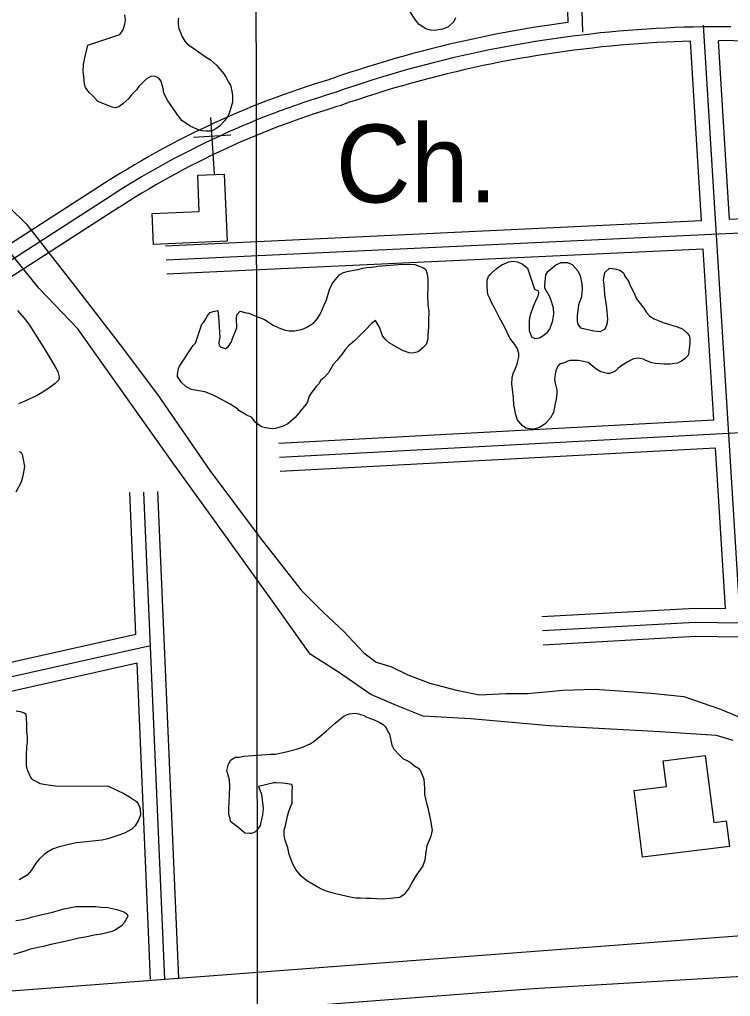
# Model space of a CAD drawing. Extents: x 3313442 to 3351311, y 721974 to 747360.
# Drawn here: x 3333060 to 3333817, y 734997 to 736038 of the extents above; entities that cross this region are included whole.
import ezdxf

# ---------------------------------------------------------------- set-up
doc = ezdxf.new("R2010")
doc.units = 0
for name, color, linetype in [('V-BLDG-OTLN', 7, 'Continuous'), ('V-GRID-MAJR', 7, 'Continuous'), ('V-ROAD-CNTR', 7, 'Continuous'), ('V-SITE-OTLN', 7, 'Continuous'), ('V-SITE-OTLN-IDEN', 7, 'Continuous'), ('V-SITE-VEGE', 7, 'Continuous'), ('V-TOPO-SHOR', 7, 'Continuous')]:
    doc.layers.add(name, color=color, linetype=linetype)

msp = doc.modelspace()

# ---------------------------------------------------------------- linework, layer by layer
at = {"layer": 'V-BLDG-OTLN'}
for points in [[(3333277.6, 735873.2), (3333280.7, 735801.7), (3333202.4, 735798.3), (3333201, 735831.3), (3333251.1, 735833.4), (3333249.4, 735872)], [(3333723.4, 735145.6), (3333714.4, 735216.9), (3333749, 735221.2), (3333745.6, 735248.3), (3333790.3, 735253.9), (3333799.3, 735182.6), (3333812.6, 735184.3), (3333816, 735157.3)]]:
    msp.add_lwpolyline(points, close=True, dxfattribs=at)
at = {"layer": 'V-GRID-MAJR'}
msp.add_spline([(3333324.1, 727373.9), (3333315.3, 733432.2), (3333306.5, 739494), (3333297.7, 745555.7), (3333297.7, 745559.2)], degree=3, dxfattribs=at)
at = {"layer": 'V-ROAD-CNTR'}
for points in [[(3333636.2, 737279.2), (3333654.9, 736173.7), (3333659.3, 736024.5)], [(3333638.9, 736236.6), (3333639.9, 736173.3), (3333644, 736034.9)], [(3333644, 736034.9), (3333616.8, 736030.8), (3333606.8, 736029.3), (3333596.9, 736027.6), (3333587, 736025.9), (3333577, 736024.1), (3333567.1, 736022.2), (3333557.2, 736020.2), (3333547.4, 736018.2), (3333537.5, 736016.1), (3333527.7, 736013.9), (3333517.8, 736011.6), (3333508, 736009.2), (3333498.2, 736006.8), (3333488.5, 736004.3), (3333478.7, 736001.7), (3333469, 735999), (3333459.3, 735996.3), (3333449.6, 735993.4), (3333440, 735990.5), (3333430.3, 735987.6), (3333420.7, 735984.5), (3333411.1, 735981.4), (3333401.6, 735978.2), (3333392.1, 735974.9), (3333389.5, 735974)], [(3333817.6, 736030.2), (3333807.7, 736030.3), (3333797.7, 736030.2), (3333787.7, 736030.1), (3333777.8, 736029.9), (3333767.8, 736029.7), (3333757.9, 736029.3), (3333747.9, 736028.9), (3333738, 736028.4), (3333728, 736027.8), (3333718.1, 736027.1), (3333708.1, 736026.4), (3333698.2, 736025.5), (3333688.3, 736024.6), (3333678.4, 736023.6), (3333668.5, 736022.5), (3333658.6, 736021.4), (3333648.7, 736020.2), (3333638.8, 736018.9), (3333628.9, 736017.5), (3333619.1, 736016), (3333609.2, 736014.5), (3333599.4, 736012.8), (3333589.6, 736011.1), (3333579.8, 736009.3), (3333570, 736007.5), (3333560.2, 736005.5), (3333550.5, 736003.5), (3333540.7, 736001.4), (3333531, 735999.3), (3333521.3, 735997), (3333511.6, 735994.7), (3333501.9, 735992.3), (3333492.3, 735989.8), (3333482.6, 735987.2), (3333473, 735984.6), (3333463.5, 735981.9), (3333453.9, 735979.1), (3333444.3, 735976.2), (3333434.8, 735973.3), (3333425.3, 735970.2), (3333415.9, 735967.1), (3333406.4, 735964), (3333397, 735960.7), (3333394.4, 735959.8)], [(3333827.7, 735395.4), (3333788.5, 736031.8)], [(3333774.5, 736015), (3333748.6, 736013.9), (3333738.8, 736013.4), (3333729, 736012.8), (3333719.1, 736012.1), (3333709.3, 736011.4), (3333699.5, 736010.6), (3333689.7, 736009.7), (3333679.9, 736008.7), (3333670.1, 736007.6), (3333660.4, 736006.5), (3333650.6, 736005.3), (3333640.8, 736004), (3333631.1, 736002.6), (3333621.3, 736001.2), (3333611.6, 735999.7), (3333601.9, 735998), (3333592.2, 735996.4), (3333582.5, 735994.6), (3333572.8, 735992.8), (3333563.2, 735990.8), (3333553.6, 735988.9), (3333543.9, 735986.8), (3333534.3, 735984.6), (3333524.7, 735982.4), (3333515.2, 735980.1), (3333505.6, 735977.7), (3333496.1, 735975.3), (3333486.6, 735972.7), (3333477.1, 735970.1), (3333467.6, 735967.4), (3333458.2, 735964.7), (3333448.7, 735961.9), (3333439.3, 735958.9), (3333429.9, 735956), (3333420.6, 735952.9), (3333411.3, 735949.8), (3333401.9, 735946.5), (3333399.4, 735945.6)], [(3333786.3, 735823.4), (3333774.5, 736015)], [(3333856.9, 736014.2), (3333847, 736014.6), (3333837.2, 736014.9), (3333804.5, 736015.6)], [(3333816.2, 735824.8), (3333804.5, 736015.4)], [(3333390.1, 735974.1), (3333381.8, 735971.6), (3333373.4, 735969), (3333365.1, 735966.3), (3333356.8, 735963.5), (3333348.5, 735960.6), (3333340.3, 735957.7), (3333332, 735954.7), (3333323.8, 735951.6), (3333315.7, 735948.4), (3333307.5, 735945.2), (3333299.4, 735941.8), (3333291.4, 735938.5), (3333283.3, 735935), (3333275.3, 735931.4), (3333267.3, 735927.8), (3333259.4, 735924.1), (3333251.5, 735920.4), (3333243.6, 735916.5), (3333235.8, 735912.6), (3333228, 735908.6), (3333220.2, 735904.6), (3333212.5, 735900.4), (3333204.8, 735896.2), (3333197.2, 735892), (3333189.6, 735887.6), (3333182, 735883.2), (3333174.5, 735878.7), (3333167, 735874.2), (3333159.6, 735869.6), (3333152.2, 735864.9), (3333149.1, 735862.9)], [(3333394.4, 735959.8), (3333386.2, 735957.3), (3333378, 735954.7), (3333369.8, 735952), (3333361.6, 735949.3), (3333353.5, 735946.5), (3333345.4, 735943.6), (3333337.3, 735940.6), (3333329.2, 735937.6), (3333321.2, 735934.5), (3333313.2, 735931.3), (3333305.2, 735928), (3333297.2, 735924.7), (3333289.3, 735921.2), (3333281.5, 735917.8), (3333273.6, 735914.2), (3333265.8, 735910.6), (3333258, 735906.9), (3333250.3, 735903.1), (3333242.6, 735899.2), (3333234.9, 735895.3), (3333227.2, 735891.3), (3333219.6, 735887.3), (3333212.1, 735883.1), (3333204.6, 735878.9), (3333197.1, 735874.6), (3333189.6, 735870.3), (3333182.2, 735865.9), (3333174.9, 735861.4), (3333167.6, 735856.9), (3333160.3, 735852.2), (3333157.2, 735850.3)], [(3333398.8, 735945.5), (3333390.6, 735943), (3333382.6, 735940.4), (3333374.5, 735937.8), (3333366.4, 735935.1), (3333358.4, 735932.3), (3333350.5, 735929.5), (3333342.5, 735926.6), (3333334.6, 735923.6), (3333326.7, 735920.5), (3333318.8, 735917.4), (3333310.9, 735914.1), (3333303.1, 735910.9), (3333295.3, 735907.5), (3333287.6, 735904.1), (3333279.9, 735900.6), (3333272.2, 735897), (3333264.5, 735893.3), (3333256.9, 735889.6), (3333249.3, 735885.8), (3333241.8, 735882), (3333234.3, 735878.1), (3333226.8, 735874.1), (3333219.3, 735870), (3333211.9, 735865.9), (3333204.6, 735861.7), (3333197.3, 735857.4), (3333190, 735853), (3333182.7, 735848.6), (3333175.5, 735844.2), (3333168.4, 735839.6), (3333165.3, 735837.6)], [(3333149.1, 735862.9), (3332982.5, 735755.7)], [(3333157.2, 735850.3), (3332990.6, 735743)], [(3334322.7, 735848.6), (3333816.2, 735824.8)], [(3333165.3, 735837.6), (3332998.7, 735730.4)], [(3334341.3, 735834.5), (3333215.9, 735781.6)], [(3333786.3, 735823.4), (3333215.1, 735796.5)], [(3333788.1, 735793.5), (3333216.6, 735766.6)], [(3333799.3, 735611.6), (3333788.1, 735793.5)], [(3333336.5, 735571.8), (3334253.7, 735620.9), (3334301.8, 735621.9)], [(3333335.7, 735586.8), (3333799.3, 735611.6)], [(3333337.3, 735556.8), (3333801.2, 735581.7)], [(3333811.7, 735410.7), (3333801.2, 735581.7)], [(3333183.4, 735382.9), (3333176.9, 735534.1)], [(3333214.2, 735015.9), (3333191.9, 735534.7)], [(3333229.2, 735016.5), (3333206.9, 735535.4)], [(3333616, 735402), (3333779.3, 735411.1), (3333811.7, 735410.7)], [(3333616.8, 735387.1), (3333779.7, 735396.1), (3333968.8, 735393.4), (3334181.5, 735402)], [(3333183.4, 735382.9), (3333004.1, 735342.7), (3332892.9, 735305.9)], [(3333617.6, 735372.1), (3333780, 735381.1), (3333969, 735378.4), (3334182.1, 735387)], [(3333199, 735371), (3333008.1, 735328.2), (3332897.6, 735291.7)], [(3333184.7, 735352.4), (3333012.1, 735313.7), (3332902.3, 735277.4)], [(3333199.2, 735015.3), (3333184.7, 735352.4)], [(3329842.9, 734845.2), (3331486.6, 734915.1), (3332609.5, 734970.1), (3334307.5, 735098.7), (3334855.8, 735124.8)], [(3334875.4, 735080.3), (3333607.3, 735005.4), (3332547.3, 734924.9), (3331216.9, 734855.5), (3329722.8, 734799.3)]]:
    msp.add_lwpolyline(points, dxfattribs=at)
at = {"layer": 'V-SITE-OTLN'}
for p, q in [((3333267.2, 735873.6), (3333263.5, 735933.5)), ((3333284.7, 735914.7), (3333244.8, 735912.3))]:
    msp.add_line(p, q, dxfattribs=at)
at = {"layer": 'V-SITE-VEGE'}
for points in [[(3333524, 736039.8), (3333521.9, 736035), (3333515.8, 736029.9), (3333510.4, 736027.8), (3333501.6, 736026.2), (3333497.4, 736026.5), (3333492.4, 736028.2), (3333485.5, 736032.6), (3333481.9, 736036.8), (3333475.9, 736046.2)], [(3333240.8, 736010.2), (3333246.5, 736006.4), (3333250.1, 736003.5), (3333257.2, 735998.5), (3333263.2, 735995), (3333269.5, 735989.4), (3333277.2, 735980), (3333279.6, 735976.1), (3333282.1, 735971.4), (3333284.2, 735967.9), (3333285.7, 735961.7), (3333286.3, 735956.9), (3333286.4, 735949.8), (3333282.9, 735937.9), (3333280.9, 735933.8), (3333277.9, 735929.9), (3333272.7, 735924.5), (3333268.8, 735921.5), (3333263.8, 735919.1), (3333258.5, 735919.1), (3333254.3, 735919.3), (3333248.4, 735921), (3333241.2, 735924.2), (3333232.3, 735930.4), (3333227.8, 735936.3), (3333221.8, 735945.4), (3333217.6, 735951.3), (3333213.4, 735959.6), (3333212.5, 735964.6), (3333210.6, 735972.3), (3333207.6, 735975.9), (3333203.5, 735977.6), (3333199.3, 735977.3), (3333194.3, 735974.3), (3333186.6, 735966.5), (3333184, 735963.2), (3333179, 735957.8), (3333176.1, 735954), (3333169.6, 735948), (3333165.5, 735945), (3333161.9, 735943.8), (3333158.4, 735944.6), (3333142.9, 735950.7), (3333137.5, 735956.6), (3333133.6, 735960.4), (3333129.7, 735965.4), (3333128.8, 735969), (3333127.9, 735977), (3333127.5, 735982.9), (3333127.8, 735990), (3333129.2, 735997.2), (3333132.3, 736010.5), (3333166.3, 736022.1), (3333169.9, 736026.8), (3333171.9, 736033.1), (3333172.4, 736037.2), (3333171.8, 736042.9)], [(3333229, 736039.5), (3333228.5, 736037.4), (3333228.5, 736032.6), (3333229.1, 736028.5), (3333231.6, 736022.3), (3333232.5, 736020.2), (3333235.8, 736014.9), (3333237.6, 736012.6), (3333240.8, 736010.2)], [(3333341.7, 735707.5), (3333347, 735706.3), (3333352.1, 735706.4), (3333358.3, 735707.3), (3333362.1, 735708.5), (3333366.3, 735710.6), (3333373, 735714.8), (3333376.9, 735719.6), (3333379.2, 735723.2), (3333381.2, 735727.1), (3333384.2, 735733.9), (3333386.8, 735739.3), (3333390.2, 735751.4), (3333392.9, 735756.8), (3333395.8, 735760.7), (3333400.8, 735766.4), (3333404.9, 735768.5), (3333410, 735770), (3333420, 735771.8), (3333425.3, 735773.1), (3333429.2, 735773.7), (3333435.1, 735774.3), (3333441.6, 735775.3), (3333454.4, 735776.3), (3333463, 735777.2), (3333476, 735777.3), (3333480.7, 735777.1), (3333490, 735773.6), (3333492, 735772.1)], [(3333646.1, 735674.7), (3333644, 735674), (3333641.1, 735672.8), (3333635.1, 735670.7), (3333633.1, 735668.6), (3333631.1, 735663.6), (3333630.2, 735660.3), (3333629.6, 735654.7), (3333630.3, 735650.5), (3333632.1, 735643.7), (3333632.1, 735639.6), (3333631.3, 735633.6), (3333630.4, 735628.9), (3333628.4, 735619.4), (3333625.5, 735613.7), (3333620.2, 735607.8), (3333614.3, 735603.6), (3333608.1, 735601.7), (3333605.2, 735601.7), (3333599.2, 735602.8), (3333595.1, 735605.5), (3333590.3, 735611.7), (3333588.4, 735617), (3333586.3, 735627.9), (3333585.9, 735635), (3333584.7, 735644.2), (3333584, 735649.8), (3333584.6, 735656.4), (3333585.7, 735661.1), (3333587.8, 735665.6), (3333589.8, 735671.2), (3333591.5, 735678.4), (3333591.5, 735682.2), (3333590.3, 735687.2), (3333587.5, 735691.7), (3333582.2, 735698.4), (3333576.4, 735710.6), (3333570.7, 735720.9), (3333565.9, 735730), (3333562, 735737.1), (3333560.8, 735740.7), (3333558.7, 735745.1), (3333557.7, 735753.4), (3333557.9, 735760.5), (3333559.4, 735764.1), (3333560.9, 735766.5), (3333567.6, 735772.4), (3333573.5, 735776.6), (3333580.9, 735780), (3333585.9, 735780.6), (3333589.8, 735779.7), (3333595.2, 735777.7), (3333600.8, 735773)], [(3333600.8, 735773), (3333608.4, 735750.8), (3333612.3, 735748.8), (3333612.6, 735746.7), (3333611.7, 735743.4), (3333609.4, 735737.8), (3333606.8, 735732.4), (3333603.6, 735723.2), (3333602.8, 735717.6), (3333602.8, 735706.9), (3333605, 735700.1), (3333608.8, 735698.1), (3333613.6, 735699), (3333617.1, 735701.1), (3333622.1, 735705), (3333624.8, 735708.3), (3333627.7, 735717.2), (3333628.8, 735724.6), (3333628.7, 735730.5), (3333626.6, 735737.6), (3333624.5, 735742.7), (3333619.4, 735751.8), (3333619.3, 735755.1), (3333620.4, 735766), (3333622.5, 735769.6), (3333631, 735776.8), (3333636.6, 735779.2), (3333643.5, 735779), (3333648.5, 735776.9), (3333654.5, 735770.2), (3333656.9, 735764.9), (3333658.8, 735756.3), (3333659.1, 735751.2), (3333658.3, 735742.6), (3333655.1, 735734), (3333653.7, 735722.4), (3333653.7, 735716.5), (3333654.4, 735713.3), (3333657.4, 735709.7), (3333671.6, 735706.3), (3333678.7, 735705.7), (3333683.5, 735708.5), (3333685.8, 735713.5), (3333686.3, 735718.6), (3333685.7, 735727.1), (3333685, 735733.7), (3333683.2, 735744.9), (3333682.8, 735751.4), (3333682.2, 735758.2), (3333681.9, 735760.3), (3333683.3, 735768.6), (3333688.3, 735773.1), (3333693.9, 735772.3), (3333699.3, 735771.1), (3333703.1, 735768.2), (3333704.6, 735764.6), (3333708.5, 735759.3), (3333710.4, 735754.6), (3333714.3, 735747.2), (3333717, 735740.4), (3333724.8, 735730.4), (3333727.8, 735726), (3333731.1, 735721.9), (3333735.8, 735719), (3333739.4, 735717.8), (3333745.4, 735715.2), (3333760.5, 735710.6), (3333766.2, 735708.5), (3333770.6, 735704.4), (3333773.3, 735701.5), (3333773.9, 735698.2), (3333774, 735693.2), (3333772.9, 735684.3), (3333772.6, 735680.7), (3333768.8, 735676.8), (3333764.9, 735674.1), (3333760.8, 735672), (3333752.5, 735670.8), (3333746.6, 735670.7), (3333737.1, 735671.5), (3333733.2, 735672.4), (3333727, 735674.7), (3333724.3, 735676.2), (3333719, 735677.3), (3333713.9, 735676.4), (3333711, 735675.2), (3333707.7, 735673.4), (3333701.3, 735669.5), (3333697.1, 735666.2), (3333693.9, 735663.2), (3333688.3, 735661.1), (3333686.2, 735661), (3333681.8, 735661.9), (3333679.1, 735662.8), (3333674.9, 735665.1), (3333671.9, 735667.2), (3333667.7, 735671), (3333665.4, 735672.7), (3333658.8, 735674.2), (3333654.7, 735674.7), (3333646.1, 735674.7)], [(3333492, 735772.1), (3333493.9, 735767.1), (3333494.5, 735761.2), (3333494.6, 735751.4), (3333494.3, 735744.9), (3333494.7, 735734.2), (3333495.7, 735727.1), (3333495.5, 735717), (3333495.5, 735710.8), (3333494.7, 735701.6), (3333494.7, 735697.4), (3333492.7, 735691.8), (3333489.8, 735688.5), (3333484.5, 735684), (3333478.8, 735682.5), (3333474.7, 735683.1), (3333467.5, 735685.4), (3333453.5, 735693.6), (3333450.3, 735696.5), (3333446.4, 735701.2), (3333443, 735710.4), (3333441.2, 735713), (3333438.8, 735717.2), (3333434.7, 735714.2), (3333432.9, 735712.4), (3333430, 735709.1), (3333425.9, 735705.2), (3333420, 735699.2), (3333416.8, 735696.2), (3333410, 735690.5), (3333406.8, 735686.7), (3333403, 735681), (3333397.7, 735674.7), (3333393.9, 735670.6), (3333388.9, 735661.6), (3333383.9, 735656.2), (3333380.7, 735653.8), (3333378.3, 735650), (3333375.7, 735647), (3333371, 735641), (3333368.3, 735636.9), (3333366.3, 735630.6), (3333364.6, 735627.9), (3333357.8, 735619.9), (3333353.4, 735614.2), (3333345.5, 735607.3), (3333340.4, 735604.9), (3333332.2, 735602.2), (3333328.6, 735602.1), (3333321.5, 735603), (3333317.3, 735604.1), (3333313.4, 735606.8), (3333311.1, 735608.8), (3333306.9, 735614.1), (3333301.2, 735617), (3333293.2, 735621.4), (3333291.7, 735623.2), (3333283.9, 735628.2), (3333275.6, 735632.8), (3333267.3, 735637.2), (3333263.4, 735639), (3333257.1, 735641.3), (3333242.3, 735643.8), (3333236.6, 735647.1), (3333232.2, 735651.2), (3333228, 735657.7), (3333227.9, 735660), (3333228.8, 735666.3), (3333229.9, 735668.9), (3333236.4, 735678.5), (3333239.9, 735684.1), (3333244.6, 735690.7), (3333246.9, 735693.4), (3333253.9, 735713.6), (3333256, 735715.7), (3333258, 735719), (3333260.3, 735723.1), (3333262.7, 735725.8), (3333265.9, 735727), (3333270.7, 735728), (3333271.6, 735721.4), (3333273, 735699.8), (3333271.8, 735693.9), (3333272.2, 735690.9), (3333274.2, 735688.9), (3333279, 735687.4), (3333282, 735689.5), (3333285.5, 735694.6), (3333286.3, 735698.1), (3333291, 735709.4), (3333290.9, 735719.5), (3333291.2, 735723.4), (3333294.7, 735727.3), (3333300.9, 735725.5), (3333303.9, 735725.3), (3333309, 735723.2), (3333312.5, 735721.5), (3333320.6, 735718.3), (3333329.8, 735712.4), (3333335.7, 735709.5), (3333341.7, 735707.5)], [(3333057.5, 735727.9), (3333064.4, 735720), (3333069.3, 735713.5), (3333076.3, 735702.8), (3333085.4, 735688.1), (3333090.9, 735679.5), (3333097.2, 735668.9), (3333100.4, 735663.1), (3333101.8, 735657.2), (3333101.5, 735654.1), (3333097.4, 735650.3), (3333093.3, 735647.2), (3333084.4, 735640.9), (3333077.5, 735637), (3333065.1, 735631.4), (3333058.3, 735628.6)], [(3333059.4, 735578), (3333061.1, 735576.9), (3333062.2, 735574.5), (3333063.9, 735567.7), (3333064.7, 735561.8), (3333063, 735552.1), (3333061.4, 735545.2), (3333055.6, 735534.5)], [(3333056.1, 735301.6), (3333060.2, 735300.9), (3333064.4, 735299.6), (3333066.1, 735298.5), (3333066.9, 735288.6), (3333066.9, 735279.3), (3333067.7, 735274.4), (3333067.7, 735267.9), (3333067.1, 735263.7), (3333066.5, 735253.7), (3333066.5, 735244.1), (3333066.9, 735241.7), (3333068, 735237.9), (3333071.5, 735230.4), (3333074.2, 735228), (3333079.8, 735225.3), (3333081.5, 735224.2)], [(3333474.8, 735113), (3333469.5, 735105.9), (3333464.8, 735102.9), (3333454.5, 735101.6), (3333446.2, 735101.2), (3333434.3, 735101.7), (3333429.3, 735101.7), (3333423, 735102.2), (3333418, 735102.2), (3333411.8, 735103), (3333407.3, 735104.2), (3333398.1, 735106.2), (3333393.6, 735107.3), (3333387.7, 735109.1), (3333382.9, 735111.1), (3333376.7, 735114), (3333368.1, 735119.3), (3333365.1, 735121.3), (3333359.7, 735125.5), (3333354, 735132.5), (3333350.7, 735138.4), (3333346.8, 735148.5), (3333345.5, 735155.6), (3333342.5, 735163.8), (3333341.6, 735168.9), (3333341.5, 735174.8), (3333343, 735179.3), (3333345, 735189.4), (3333346.1, 735193.2), (3333348.4, 735199.2), (3333349.9, 735203.3), (3333350.1, 735210.2), (3333350.1, 735215.2), (3333350.3, 735220.8), (3333349.7, 735223.2), (3333342.6, 735224.3), (3333339.9, 735224.6), (3333332.5, 735225.1), (3333330.4, 735225.1), (3333314.2, 735221.1), (3333317.2, 735212.8), (3333319.1, 735198), (3333318.6, 735190.9), (3333317.4, 735185.9), (3333316.6, 735183.2), (3333316, 735179.6), (3333312.5, 735174.6), (3333310.1, 735172.5), (3333306.6, 735171), (3333304.2, 735171), (3333299.5, 735171.2), (3333291.7, 735178), (3333284.8, 735183.5), (3333282.7, 735192.1), (3333282.7, 735197.2), (3333282.9, 735205.2), (3333283.4, 735211.4), (3333283.6, 735221.5), (3333283.3, 735228), (3333280.5, 735238), (3333281.7, 735243.7), (3333284.3, 735249), (3333286.1, 735250.2), (3333289.3, 735252.1), (3333293.5, 735252.4), (3333298.5, 735253.3), (3333326.9, 735255.3), (3333332, 735255.4), (3333343.8, 735257.8), (3333354.8, 735260.9), (3333361, 735263), (3333369.2, 735266.6), (3333373.4, 735269.3), (3333381.6, 735275.9), (3333386.6, 735280.4), (3333396, 735288.5), (3333405.5, 735296.3), (3333410.8, 735298.4), (3333417.6, 735299), (3333420.6, 735298.5), (3333426.5, 735296.7), (3333429.5, 735295), (3333437.5, 735292.1), (3333442.9, 735289.7), (3333447, 735287.1), (3333449.1, 735285.1), (3333450.9, 735282.1), (3333452.1, 735279.7), (3333453.9, 735276.8), (3333456.4, 735265), (3333458.5, 735260.8), (3333464.5, 735254.3), (3333468.4, 735250.5), (3333473.4, 735248.2), (3333477.6, 735245.6), (3333480.6, 735243.2), (3333484.8, 735240.6), (3333486.9, 735237.6), (3333489.3, 735231.7), (3333490.2, 735228.8), (3333491.2, 735219.3)], [(3333081.5, 735224.2), (3333087.4, 735223.2), (3333092.6, 735222.3), (3333100.8, 735221.3), (3333151.5, 735221.7), (3333154.2, 735221.4), (3333163.2, 735217.3), (3333170.5, 735213.6), (3333176.7, 735210.2), (3333184, 735205.1), (3333185.8, 735202.7), (3333187.5, 735199.2), (3333188.2, 735196.8), (3333188.6, 735191), (3333186.6, 735185.8), (3333182.8, 735179.2), (3333179.1, 735175.7), (3333171.2, 735171.2), (3333165.3, 735169.1), (3333153.7, 735165.2), (3333147.5, 735163.8), (3333120.3, 735161.1), (3333112, 735159.3), (3333100.7, 735156.5), (3333094.8, 735154.4), (3333088.6, 735150.9), (3333085.6, 735148.5), (3333080.4, 735143.6), (3333077, 735139.4), (3333072.3, 735131.8), (3333067.5, 735126.6), (3333059.2, 735121.7)], [(3333491.2, 735219.3), (3333491.2, 735212.5), (3333493.1, 735203.3), (3333494.6, 735198.3), (3333497.4, 735184.7), (3333499.2, 735174.6), (3333497.8, 735168.1), (3333493.7, 735157.7), (3333492.6, 735151.4), (3333491.5, 735142.5), (3333489.4, 735136.6), (3333482.7, 735127), (3333478, 735119), (3333474.8, 735113)], [(3333163.2, 735090.1), (3333170.8, 735087.5), (3333173.9, 735085.4), (3333175, 735083), (3333174, 735080.9), (3333170.9, 735075.7), (3333168.2, 735072.6), (3333161.3, 735068.1), (3333156.9, 735066.3), (3333146.9, 735063.8), (3333139, 735062.7), (3333129.7, 735060.6), (3333122.8, 735059.5), (3333112.8, 735057), (3333104.9, 735055.2), (3333092.9, 735052.7), (3333084.6, 735050.6), (3333070.9, 735047.7), (3333065, 735045.6), (3333053, 735042.1)], [(3333055.5, 735078.3), (3333061, 735079), (3333069.2, 735080.8), (3333073, 735082.2), (3333079.5, 735083.6), (3333083.7, 735084.7), (3333095, 735087.2), (3333101.9, 735089.3), (3333107, 735090.7), (3333119.4, 735093.2), (3333130.5, 735093.3), (3333140.8, 735093.1), (3333146, 735092.4), (3333153.6, 735092.1), (3333163.2, 735090.1)]]:
    msp.add_lwpolyline(points, dxfattribs=at)
at = {"layer": 'V-TOPO-SHOR'}
for points in [[(3333012.1, 735873.3), (3333066.6, 735820.5), (3333118.9, 735753.7), (3333166.7, 735691.3), (3333206.7, 735638.5), (3333262.4, 735557.5), (3333315.9, 735486), (3333359.6, 735430.1), (3333383.1, 735406.8), (3333405, 735386.1), (3333426.4, 735363.3), (3333439.7, 735353.5), (3333455.3, 735348.7), (3333473.3, 735340), (3333496.9, 735331.2), (3333525.1, 735323.5), (3333549.7, 735318.8), (3333577.8, 735320.1), (3333601.2, 735320.2), (3333638.8, 735323.6), (3333672.4, 735324.7), (3333698.8, 735323), (3333732.7, 735320.6), (3333767.5, 735316.9), (3333806.7, 735303.3), (3333831, 735293.2)], [(3333820.1, 735270.1), (3333802.4, 735275.4), (3333742.1, 735279.4), (3333624.4, 735285.8), (3333540.3, 735293.2), (3333489.8, 735296.1), (3333461.2, 735307.2), (3333433.9, 735319.2), (3333399.3, 735342.8), (3333369.3, 735362.1), (3333329, 735418.3), (3333262.6, 735510.7), (3333222.3, 735566.9), (3333121.7, 735708.5), (3333080.5, 735751.5), (3333035.5, 735806.6)]]:
    msp.add_lwpolyline(points, dxfattribs=at)

# ---------------------------------------------------------------- texts
at = {"layer": 'V-SITE-OTLN-IDEN'}
msp.add_text('Ch.', height=83, dxfattribs=at).set_placement((3333396.3, 735843.1))

doc.saveas('drawing.dxf')
